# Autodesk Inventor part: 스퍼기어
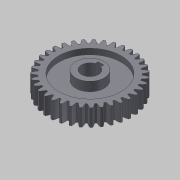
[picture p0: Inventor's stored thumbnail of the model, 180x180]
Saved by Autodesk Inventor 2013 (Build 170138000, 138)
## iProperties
Created: 2013-08
Part Number: 스퍼기어
Material: 강
Document SubType Name: Modeling
Designer: 한국산업디자인학원
Categories: <?xml version="1.0" encoding="UTF-16"?> <MemberInstance><Categories><FamilyTemplate><FamilyTemplateParameter ValueType="xs:double" Id="1" ObjectReferenceKey="da
Density: 1 g/cm^3
CustomPartVersion: 1
Author: 한국산업디자인학원
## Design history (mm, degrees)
sketch "Sketch1"
  geometry: C1 r 37 at (0, 0)
  constraints: 1 centre point
  dimensions: "d0" = 74 diameter of C1 (= da_da)
extrude "Extrusion1" new body sketch "Sketch1" distance "d1" = 15 (= da_b); taper "d2" = 0 deg
workplane "Work Plane2"
feature "피치 지름" dims "d4" = 10, "d5" = 0
workplane "Work Plane8"
workplane "Work Plane9"
feature "스퍼 기어" dims "da_b" = 15, "da_d" = 70, "da_aw" = 70, "da_da" = 74, "da_df" = 65, "da_dw" = 70, angle "da_beta" = 0 deg, "da_lefttooth" = 0, "da_righttooth" = 0
sketch "스케치3"
  geometry: L1 (0, 18)-(0, -13); L2 (0, -13)-(12.5, -13); L3 (12.5, -13)-(12.5, 18); L4 (12.5, 18)-(0, 18); 1 further point
  constraints: 8 end point, 2 perpendicular, 1 parallel, 1 vertical, 1 vertical alignment
  dimensions: "d49" = 31 distance of L1.start L1.end; "d51" = 18 distance of L1.start point (0, 0); "d52" = 25 diameter of L3 L1
revolve "회전1" sketch "스케치3" stored, may be unused: angle "d53" = 90 deg
sketch "스케치4"
  geometry: L1 (-12.5, 18)-(12.5, 18) reference; L2 (-12.5, -13)-(12.5, -13) reference; L3 (0, 18)-(0, -13); L4 (0, -13)-(7.5, -13); L5 (7.5, -13)-(7.5, 18); L6 (7.5, 18)-(0, 18); L7 (12.5, 18)-(12.5, 15) reference; L8 (12.5, 0)-(12.5, -13) reference; L9 (12.5, 15)-(27.5, 15); L10 (27.5, 15)-(27.5, 10); L11 (27.5, 10)-(12.5, 10); L12 (12.5, 10)-(12.5, 15); L13 (12.5, 0)-(27.5, 0); L14 (27.5, 0)-(27.5, 5); L15 (27.5, 5)-(12.5, 5); L16 (12.5, 5)-(12.5, 0); 1 further point
  constraints: 24 end point, 4 parallel, 3 collinear, 3 perpendicular, 2 horizontal, 2 midpoint, 2 point on line
  dimensions: "d54" = 15 diameter of L5 L3; "d55" = 55 diameter of L10 L3; "d56" = 5 distance of L9.end L10.end
revolve "회전2" sketch "스케치4" stored, may be unused: angle "d57" = 90 deg
sketch "스케치5"
  geometry: L1 (-7.5, -13)-(-7.5, 18) reference; L2 (-12.5, 18)-(12.5, 18) reference; L3 (-12.5, -13)-(12.5, -13) reference; L4 (0, 18)-(9.8, 18); L5 (9.8, 18)-(9.8, -13); L6 (9.8, -13)-(0, -13); L7 (0, -13)-(0, 18); 1 further point
  constraints: 8 end point, 2 parallel, 1 horizontal, 1 midpoint, 1 perpendicular, 1 point on line
  dimensions: "d58" = 17.3 distance between parallel lines of L1 L5
extrude "돌출2" cut sketch "스케치5" stored distance "d59" = 5; taper "d60" = 0 deg
body "Solid1"
sketch "Sketch2"
  geometry: C1 r 37 at (0, 0) reference; C2 r 35 at (0, 0)
  constraints: 1 centre point, 1 coincident
  dimensions: "d3" = 70 diameter of C2 (= da_dw)
body "Srf1"
other parameters: "d17" = 0, "d34" = 0.8976 (computed from da_z), "d39" = 0, "d41" = 0, "d47" = 0, "d48" = 0
